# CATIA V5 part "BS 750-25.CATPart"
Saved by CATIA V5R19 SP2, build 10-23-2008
Part number: BS 750-25
Bounding box of the stored display mesh (mm): x -22.494 to 22.494, y -22.494 to 22.494, z 0 to 82
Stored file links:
  C:\Users\Bora\Desktop\3D Katı model\BS serisi\BS 750\BS 750-25.CATPart
  C:\Program Files\Dassault Systemes\B19\intel_a\reffiles\standard\MetricThickPitch.txt
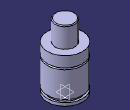
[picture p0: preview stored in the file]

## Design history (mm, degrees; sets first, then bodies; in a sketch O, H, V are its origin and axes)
Body1 (main body)
  Sketch1 on yz-plane, origin (0, 0, 0), H (0, 1, 0), V (0, 0, 1)
    point P3 (12.5, 81)
    point P5 (12.5, 81)
    point P7 (22.5, 42.5)
    point P8 (22.5, 40.5)
    point P12 (22.5, 40.5)
    point P13 (22.5, 42.5)
    line L1 (22.5, 0) -> (22.5, 4)
    line L2 (12.5, 81) -> (12.5, 56)
    arc A1 centre (11.5, 81) radius 1 from (12.5, 81) to (11.5, 82) ccw
    arc A2 centre (22.5, 41.5) radius 1 from (22.5, 42.5) to (22.5, 40.5) ccw
    line L3 (20, 7.5) -> (20, 4)
    line L4 (22.5, 7.5) -> (22.5, 40.5)
    line L5 (22.5, 42.5) -> (22.5, 56)
    line L6 (11.5, 82) -> (0, 82)
    point P15 (0, 82)
    line L7 (12.5, 56) -> (22.5, 56)
    line L8 (0, 0) -> (22.5, 0)
    line L9 (20, 7.5) -> (22.5, 7.5)
    line L10 (20, 4) -> (22.5, 4)
    coincidence: P15 V, P3 P5, P7 P13, P8 P12
    tangency: L6 A1
    horizontal: L7 H, L8 H, L9 H, L10 H
  Shaft1: profile Sketch1, axis Sketch1.V, angle 360
  Sketch2 on face of Shaft1 from Sketch1.L8, origin (0, 0, 0), H (1, 0, 0), V (0, -1, 0)
    point P1 (10, 0)
    distance P1 V = 10
  Hole1: placed by Sketch2, at (10, 0, 0) direction (0, 0, 1), diameter 6.647, depth 4, threaded "M8", thread diameter 8, thread depth 4, pitch 1.25
  CircPattern1: of Hole1, instances 2, angular step 180, axis from xy-plane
